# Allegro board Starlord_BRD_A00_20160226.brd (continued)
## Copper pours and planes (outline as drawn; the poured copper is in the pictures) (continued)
3D3V_S5_KBC on BOTTOM: 192.45,41.06 192.35,41.16 192.35,43.93 192.53,44.11 195.71,44.11 195.98,43.83 195.98,43.35 195.48,42.84 193.06,42.84 192.89,42.66 192.89,41.67 192.94,41.62 192.94,41.14 192.86,41.06
3D3V_S5_KBC on L5VCC: 186.31,27.08 186.04,27.35 186.04,28.33 186.69,28.99 191.39,28.99 192.01,29.6 192.01,32.43 189.74,34.7 186.82,34.7 185.17,36.35 181.45,36.35 179.69,34.59 179.69,29.89 179.04,29.24 178.82,29.24 178.55,29.51 178.55,36.84 185.04,43.34 187.45,43.34 190.07,45.95 194.55,45.95 194.55,42.3 197.85,39 197.85,37.73 200.9,34.68 200.9,33.7 200.5,33.3 199.9,33.3 197.87,35.34 196.19,35.34 194.92,34.07 194.15,34.07 192.77,32.68 192.77,29.13 191.87,28.22 187.93,28.22 186.79,27.08
3D3V_S5_PCH on TOP: 93.78,30.83 93.7,30.9 93.7,31.84 93.9,32.05 95.1,32.05 95.22,31.92 95.22,31.21 94.84,30.83
3D3V_S5_PCH on TOP: 113.69,14.01 113.43,14.27 113.43,14.34 109.47,18.3 109.47,18.89 109.65,19.07 109.78,19.07 110.67,18.18 111.61,18.18 112.72,17.06 120.72,17.06 121.03,16.76 121.03,15.97 120.83,15.76 120.57,15.76 120.47,15.87 120.47,16.15 120.29,16.32 115.03,16.32 114.3,15.59 114.3,14.27 114.04,14.01
3D3V_S5_PCH on TOP: 112.7,27.35 111.94,28.11 111.94,30.09 111.66,30.37 111.07,30.37 110.84,30.14 108.02,30.14 107.08,31.08 107.08,31.54 104.93,33.7 100.99,33.7 100.79,33.49 99.87,33.49 99.62,33.75 99.62,34.21 100.2,34.79 105.31,34.79 108.96,31.13 117.35,31.13 118.16,30.32 118.16,28.97 119.07,28.06 120.37,28.06 120.75,28.44 120.75,28.97 121.32,29.54 121.32,30.94 125.65,35.27 126.8,35.27 127.56,36.03 127.56,36.29 127.73,36.47 128.88,36.47 129.13,36.21 129.13,35.58 127.94,34.38 126.16,34.38 123.73,31.96 123.72,31.96 122.15,30.38 122.15,29.28 121.52,28.66 121.52,27.97 120.95,27.4 118.54,27.4 117.3,28.64 117.3,29.33 117.07,29.56 117.07,29.91 116.84,30.14 113.41,30.14 112.7,29.43 112.7,28.31 112.88,28.13 114.63,28.13 114.76,28.01 115.14,28.01 115.26,27.88 115.26,27.42 115.19,27.35
3D3V_S5_PCH on TOP: 100.61,14.04 100.51,14.14 100.51,14.32 100.76,14.57 101.24,14.57 101.42,14.75 101.42,15.87 101.47,15.92 102.28,15.92 103.05,15.16 103.05,14.19 102.89,14.04
3D3V_S5_PCH on BOTTOM: 113.59,10 113.49,10.1 113.49,11.27 113.59,11.37 113.59,14.44 113.74,14.6 114.2,14.6 114.6,14.19 115.14,14.19 115.62,13.71 115.62,13.17 114.97,12.53 114.97,11.92 114.53,11.47 114.53,10.23 114.3,10 ; 2 cut-outs
3D3V_S5_PCH on BOTTOM: 127.94,35.78 127.81,35.91 127.81,36.29 128.57,37.05 128.57,37.51 129.04,37.98 129.04,39.17 129.34,39.46 130.1,39.46 130.22,39.34 130.22,37.05 130.1,36.92 129.72,36.92 128.57,35.78
3D3V_S5_PCH on BOTTOM: 84.2,12.82 84.07,12.95 84.07,13.45 83.92,13.61 83.62,13.61 83.34,13.89 83.34,14.27 83.54,14.47 83.82,14.47 84.1,14.19 84.45,14.19 84.76,13.89 84.76,12.92 84.66,12.82
3D3V_S5_PCH on BOTTOM: 81.38,12.44 81,12.82 80.57,12.82 80.47,12.92 80.47,13.33 80.64,13.5 81.46,13.5 81.63,13.33 81.63,12.54 81.53,12.44
3D3V_S5_PCH on BOTTOM: 113.21,24.22 113.08,24.35 113.08,24.86 113.21,24.98 113.59,24.98 113.71,25.11 113.71,25.87 113.59,26 111.38,26 111.17,26.2 111.17,27.27 111.3,27.4 113.59,27.4 113.84,27.65 113.84,27.8 114.02,27.98 115.19,27.98 115.31,27.86 115.31,27.37 115.14,27.19 115.14,27.17 114.93,26.97 114.73,26.97 114.45,26.69 114.45,25.39 114.76,25.09 114.76,24.63 114.35,24.22 ; 4 cut-outs
3D3V_S5_PCH on L3: 107.62,14.39 108.2,14.98 110.11,14.98 111.73,13.35 113.66,13.35 114.15,13.83 114.15,14.55 113.97,14.72 113.59,14.72 113.23,14.37 113.23,14.16 113.08,14.01 112.11,14.01 110.29,15.84 107.11,15.84 106.68,15.41 105.69,15.41 104.85,14.57 100.71,14.57 100.51,14.37 100.51,13.89 100.58,13.81 105.31,13.81 105.89,14.39
3D3V_S5_PCH on L6: 78.97,9.95 78.76,10.15 78.76,10.63 81.89,13.76 81.89,14.14 82.29,14.55 83.72,14.55 83.92,14.34 83.92,13.58 80.29,9.95
3D3V_S5_PCH on L6: 97.2,34.54 100.18,34.54 100.61,34.1 100.61,33.65 99.97,33.01 97.1,33.01 96.7,33.42 96.7,34.03
3D3V_SEN_S0 on TOP: 56.64,91.51 56.59,91.56 56.59,92.12 56.36,92.35 56.36,92.63 55.32,93.67 54.2,93.67 52.09,95.77 52.09,98.67 52.37,98.95 54.41,98.95 54.58,98.77 54.58,98.04 55.29,97.32 56.18,97.32 56.41,97.1 56.41,94.56 56.72,94.25 56.72,93.36 57.36,92.71 57.36,92.16 57.2,91.99 57.2,91.56 57.15,91.51 ; 6 cut-outs
3D3V_SSD on TOP: 201.6,10.89 201.34,11.14 201.34,12.67 200.71,13.3 198.42,13.3 198.04,13.68 198.04,19.78 198.07,19.8 198.07,20.18 201.09,23.21 202.61,23.21 202.74,23.33 202.74,31.21 203.38,31.84 203.88,31.84 204.09,31.64 204.09,22.57 203.07,21.56 203.07,20.97 202.92,20.82 200.66,20.82 200.48,20.64 200.48,20.21 200.28,20.01 199.29,20.01 199.11,19.83 199.11,18.51 199.44,18.18 199.44,15.21 199.57,15.08 203.25,15.08 203.63,14.7 203.63,11.4 203.12,10.89 ; 11 cut-outs
3D3V_SSD on BOTTOM: 201.65,27.04 201.62,27.07 201.62,28.82 201.65,28.85 203.3,28.85 203.5,29.05 203.5,30.29 203.25,30.55 201.62,30.55 201.6,30.57 201.6,31.72 201.85,31.97 203.76,31.97 204.01,31.72 204.01,27.47 203.58,27.04
3D3V_SSD on BOTTOM: 202.11,11.9 201.6,12.41 201.6,14.32 203.5,14.32 203.63,14.19 203.63,12.28 203.25,11.9
81208_AGND on TOP: 153.74,91.3 153.69,91.36 153.69,91.76 153.92,91.98 153.92,95.62 153.91,95.62 153.91,96.85 153.68,97.08 153.38,97.08 153.11,97.35 153.11,98.59 152.93,98.77 152.75,98.77 152.68,98.85 152.68,99.33 152.78,99.43 153.62,99.43 153.92,99.13 153.92,98.44 154.05,98.31 154.05,98.31 154.43,97.93 156.54,97.93 156.56,97.96 157.12,97.96 157.25,97.83 157.25,97.65 157.48,97.43 158.9,97.43 159.61,98.14 161.92,98.14 162.05,98.01 162.05,97.4 161.97,97.32 160.07,97.32 159.54,96.79 159.54,94.86 159.69,94.71 159.69,93.41 159.56,93.29 159.15,93.29 159.03,93.41 159.03,93.87 158.77,94.12 158.11,94.12 158.03,94.04 158.03,92.89 157.85,92.71 154.78,92.71 154.62,92.55 154.62,92.15 154.53,92.07 154.53,92.07 154.25,91.79 154.25,91.38 154.18,91.3 ; 25 cut-outs
81208_AGND on BOTTOM: 154.38,92.93 154.2,93.11 154.2,97.3 154.4,97.5 158.62,97.5 158.77,97.35 158.77,93.08 158.62,92.93
+DC_IN on TOP: 21.28,76.17 20.98,76.47 20.98,77.31 21.36,77.69 22.4,77.69 23.29,78.58 23.29,78.96 23.82,79.49 23.82,81.55 23.93,81.65 23.93,82.52 23.8,82.64 22.17,82.64 21.97,82.85 21.97,83.96 22.05,84.04 25.32,84.04 25.7,83.66 25.7,81.04 26.9,79.85 29.01,79.85 29.13,79.72 29.13,76.8 28.5,76.17 ; 7 cut-outs
+DC_IN on BOTTOM: 21.92,75.25 21.77,75.4 21.77,75.99 21.89,76.12 23.47,76.12 23.72,76.37 24.38,76.37 25.45,77.44 25.45,79.16 25.88,79.59 26.34,79.59 26.59,79.34 26.59,76.67 26.34,76.42 25.6,76.42 24.43,75.25
+DC_IN_C on TOP: 21.21,84.29 20.92,84.59 20.92,87.38 21.26,87.72 24.94,87.72 25.58,87.09 25.58,84.67 25.2,84.29
+DC_IN_C on BOTTOM: 18.9,81.2 18.67,81.42 18.67,82.97 19.16,83.47 19.16,83.85 20.09,84.78 20.42,84.78 20.62,84.98 20.62,87.04 21.23,87.65 23.32,87.65 23.8,87.16 23.8,84.98 23.16,84.34 22.63,84.34 22.05,83.76 21.44,83.76 20.52,82.85 20.52,82.54 20.04,82.06 20.04,81.42 19.81,81.2 ; 3 cut-outs
+SDC_IN on TOP: 32.56,81.63 32.43,81.75 32.43,83.02 31.67,83.79 31.67,86.2 31.8,86.33 34.09,86.33 34.47,85.94 38.53,85.94 38.78,85.69 38.78,83.28 38.4,82.9 36.5,82.9 35.23,81.63
+V_EDRAM_VR on TOP: 114.83,69.05 114.64,69.24 114.64,70.31 115.24,70.91 115.24,71.59 115.29,71.64 116.03,71.64 116.25,71.42 116.71,71.42 117.02,71.11 117.02,69.31 116.76,69.05 ; 3 cut-outs
+V_EDRAM_VR on TOP: 106.86,94.2 106.73,94.33 106.73,96.1 106.86,96.23 110.67,96.23 110.92,95.98 110.92,94.45 110.67,94.2
+V_EDRAM_VR on BOTTOM: 115.11,70.2 114.48,70.83 114.48,71.34 114.73,71.59 114.86,71.59 115.37,71.09 116,71.09 116.38,71.47 116.64,71.47 117.02,71.09 117.78,71.09 118.16,71.47 118.67,71.47 118.79,71.34 118.79,70.45 118.54,70.2
+V_EDRAM_VR on L4: 116.76,78.2 119.05,78.2 119.94,77.31 119.94,71.21 118.79,70.07 115.62,70.07 114.73,70.96 113.08,70.96 112.32,71.72 112.32,75.15 111.3,76.17 111.3,83.91 110.16,85.06 110.16,93.44 109.65,93.95 109.02,93.95 108.25,94.71 108.25,96.36 108.76,96.87 114.35,96.87 115.87,95.34 115.87,79.09
+V_EOPIO_VR on TOP: 106.86,91.91 106.73,92.04 106.73,93.69 106.86,93.82 109.65,93.82 109.9,93.56 109.9,92.04 109.78,91.91
+V_EOPIO_VR on TOP: 111.56,68.93 111.19,69.3 111.19,70.34 111.3,70.45 111.68,70.45 112.06,70.83 112.7,70.83 112.83,70.7 112.83,70.53 113.18,70.17 114.22,70.17 114.4,69.99 114.4,69.21 114.12,68.93 ; 3 cut-outs
+V_EOPIO_VR on BOTTOM: 111.43,69.82 111.17,70.07 111.17,70.32 111.58,70.73 111.68,70.73 111.91,70.96 111.91,71.11 111.81,71.21 111.81,71.34 111.94,71.47 112.95,71.47 113.08,71.34 113.08,70.58 112.95,70.45 112.04,70.45 112.01,70.43 112.01,69.89 111.94,69.82
+V_EOPIO_VR on L4: 107.24,93.44 109.52,93.44 109.9,93.06 109.9,84.67 110.79,83.79 110.79,76.29 111.81,75.28 111.81,71.85 112.83,70.83 112.83,69.69 112.44,69.31 110.16,69.31 108.89,70.58 108.89,74.51 108.38,75.02 108.38,80.74 106.48,82.64 106.48,92.68
AD+ on TOP: 26.97,80.1 26.85,80.23 26.85,82.97 27.1,83.23 27.1,87.82 27.18,87.9 29.69,87.9 30.53,88.74 30.53,89.53 30.94,89.93 31.09,89.93 31.29,90.14 31.29,90.9 31.42,91.02 32.05,91.02 32.31,90.77 32.31,88.48 31.55,87.72 31.55,83.66 30.78,82.9 30.78,80.48 30.4,80.1 ; 6 cut-outs
AD+ on TOP: 149.27,31.72 149.2,31.79 149.15,31.79 148.89,32.05 148.89,32.35 149.25,32.71 149.91,32.71 149.92,32.72 150.28,32.72 151.43,33.87 151.43,38.8 151.18,39.06 150.24,39.06 149.99,39.31 149.99,40.02 150.04,40.07 151.66,40.07 152.45,39.29 152.45,33.24 150.93,31.72
AD+ on BOTTOM: 147.52,29.81 147.34,29.99 147.34,30.8 147.47,30.93 147.85,30.93 148.94,32.02 148.94,32.48 148.84,32.58 148.36,32.58 148.33,32.6 148.33,33.11 148.39,33.16 149.6,33.16 149.71,33.06 149.71,31.61 149.05,30.95 148.66,30.95 148.36,30.65 148.36,30.01 148.16,29.81
AUD_AGND on TOP: 13.82,9.62 13.69,9.74 13.69,11.5 14.12,11.93 14.12,13.86 14.3,14.04 15.49,14.04 15.54,13.99 15.54,13.5 15.44,13.4 14.88,13.4 14.78,13.3 14.78,12.18 15.01,11.95 15.34,11.95 15.44,11.85 15.44,11.35 15.42,11.32 14.68,11.32 14.4,11.04 14.4,9.72 14.3,9.62
AUD_AGND on BOTTOM: 18.18,16.86 18.01,17.03 18.01,18.43 17.75,18.69 17.22,18.69 17.09,18.81 17.09,20.9 17.32,21.12 17.58,21.12 17.93,21.48 18.79,21.48 18.9,21.38 18.9,21.07 18.74,20.92 18.13,20.92 18.03,20.82 18.03,20.21 18.18,20.06 19.99,20.06 20.27,19.78 21.59,19.78 21.72,19.65 21.72,18.71 21.59,18.58 20.7,18.58 20.24,19.04 19.2,19.04 19.07,18.91 19.07,17.34 18.59,16.86 ; 9 cut-outs
AUD_AGND on L2GND: 13.59,9.68 12.96,10.32 3.3,10.32 2.53,11.09 2.53,11.98 2.98,12.22 3.3,12.63 12.9,12.63 13.87,13.38 13.41,14.51 13.41,19.57 13.87,20.7 12.9,21.45 4.15,21.45 5.84,23.14 9.65,23.14 10.03,23.52 14.73,23.52 16,24.79 18,24.79 18.02,24.78 18.02,24.3 17.88,24.16 17.5,24.16 17.13,23.79 17.13,23.16 16.75,22.78 16.75,21.98 16.99,21.75 17.91,21.75 18.27,22.11 18.27,22.87 19.16,23.76 19.16,24.52 19.56,24.92 20.04,24.92 20.54,24.41 22.48,24.41 22.61,24.54 24.61,24.54 24.62,24.52 24.62,21.73 25.12,21.24 25.5,21.24 25.51,21.22 25.51,21 25,20.49 25,19.73 24.86,19.59 21.05,19.59 20.69,19.22 20.69,15 21.05,14.63 22.2,14.63 22.34,14.49 22.34,13.38 22.08,13.13 22.08,12.49 21.94,12.35 18.77,12.35 18.51,12.09 17.88,12.09 17.24,11.46 17.15,11.46 16.64,11.97 15.97,11.97 15.46,11.46 14.7,11.46 14.34,11.09 14.34,9.7 14.32,9.68
AUD_AGND on L7GND: outline of 82 points within 2.8,10.32 29.32,25.05
AUD_SPK_L+ on TOP: 18.51,9.24 18.36,9.39 18.36,10.23 18.91,10.77 19.82,10.77 20.14,11.09 20.52,11.09 20.85,11.42 20.85,11.9 20.93,11.98 22.1,11.98 22.43,12.31 22.76,12.31 22.86,12.21 22.86,11.65 22.34,11.13 21.7,11.13 20.45,9.87 19.43,9.87 19.35,9.8 19.35,9.34 19.25,9.24 ; 3 cut-outs
AUD_SPK_L+_C on TOP: 15.34,7 14.98,7.36 14.98,7.99 16.38,9.39 16.38,9.95 16.74,10.3 17.96,10.3 18.03,10.23 18.03,9.31 17.85,9.14 17.4,9.14 16.66,8.4 16.66,7.18 16.48,7 ; 4 cut-outs
AUD_SPK_L- on TOP: 18.74,7.66 18.67,7.74 18.67,8.93 18.79,9.06 19.3,9.06 19.51,9.26 19.51,9.44 19.73,9.67 20.5,9.67 21.79,10.96 22.38,10.96 23.06,11.65 23.47,11.65 23.62,11.5 23.62,10.68 22.87,9.94 22.21,9.94 20.7,8.42 19.76,8.42 19.58,8.25 19.58,7.74 19.51,7.66 ; 3 cut-outs
AUD_SPK_L-_C on TOP: 14.46,5.59 13.92,6.14 13.92,7.69 14.07,7.84 14.58,7.84 14.91,7.51 14.91,7.28 15.47,6.72 16.58,6.72 16.89,7.03 16.89,8.25 17.35,8.7 18.29,8.7 18.36,8.63 18.36,8.14 18.46,8.04 18.46,6.93 18.36,6.82 18.01,6.82 17.85,6.67 17.85,6.19 17.26,5.59 ; 3 cut-outs
AUD_SPK_R+ on TOP: 17.65,1.92 17.5,2.07 17.5,3.34 17.78,3.62 19.33,3.62 19.92,4.22 19.92,5.21 21.36,6.65 21.36,6.85 24.92,10.41 25.27,10.41 25.6,10.08 25.6,9.85 22.43,6.67 22.43,6.34 21.46,5.38 21.46,4.89 20.98,4.41 20.98,3.62 20.14,2.79 18.62,2.79 18.46,2.63 18.46,2.4 17.98,1.92 ; 2 cut-outs
AUD_SPK_R+_C on TOP: 13.16,1.19 11.3,3.04 11.3,7.38 11.45,7.54 12.19,7.54 12.46,7.27 12.46,4.7 12.47,4.69 12.47,3.83 14.04,2.25 15.29,2.25 15.47,2.43 15.47,2.58 15.59,2.71 16.1,2.71 16.28,2.89 16.28,3.47 16.36,3.55 17.12,3.55 17.22,3.45 17.22,2.28 16.13,1.19 ; 4 cut-outs
AUD_SPK_R- on TOP: 18.49,3.83 18.34,3.98 18.34,4.94 18.08,5.2 18.08,5.63 18.21,5.76 18.82,5.76 19.3,6.24 19.3,6.34 20.72,7.76 20.72,8.09 22.22,9.59 22.78,9.59 23.77,10.58 23.77,11.93 23.9,12.06 24.46,12.06 24.53,11.98 24.53,10.25 23.29,9.01 23.16,9.01 21.13,6.98 21.13,6.62 19.77,5.26 19.77,4.35 19.25,3.83 ; 2 cut-outs
AUD_SPK_R-_C on TOP: 14.07,3.5 12.62,4.94 12.62,7.54 12.85,7.76 13.46,7.76 13.79,7.43 13.79,5.99 14.55,5.22 17.65,5.22 18.01,4.87 18.01,3.95 17.88,3.83 15.37,3.83 15.04,3.5 ; 3 cut-outs
BT+ on TOP: 154.99,25.37 154.96,25.39 153.85,25.39 153.36,25.87 153.36,28.67 154.25,29.56 158.8,29.56 158.8,29.51 159.31,29 159.31,27.04 157.63,25.37
BT+ on BOTTOM: 153.85,25.37 153.08,26.13 153.08,28.92 153.34,29.18 153.34,30.45 153.21,30.57 153.21,31.72 153.97,32.48 153.97,36.92 152.84,38.05 150.05,38.05 149.88,37.89 149.88,37.58 149.76,37.46 148.87,37.46 148.77,37.56 148.77,40.2 149.17,40.61 150.42,40.61 150.52,40.5 150.87,40.5 151.08,40.3 151.08,39.34 151.29,39.12 152.23,39.12 152.32,39.21 152.32,40.35 152.58,40.61 156.26,40.61 156.51,40.35 156.51,38.8 156.16,38.45 156.16,30.8 156.26,30.7 160.83,30.7 161.19,30.34 161.19,28.13 160.7,27.65 160.7,25.62 160.45,25.37 ; 14 cut-outs
CAP_LED#_R on L3: 194.49,31.72 194.92,31.28 194.92,30.52 194.31,29.91 193.22,29.91 191.84,31.28 191.84,32.07 191.97,32.2 192.3,32.2 192.81,31.69 193.57,31.69 193.6,31.72
CFG_RCOMP on TOP: 121.16,68.9 120.88,69.18 120.88,70.17 120.98,70.27 122.93,70.27 123.19,70.02 123.19,69.26 122.83,68.9 ; 1 cut-out
CHARGER_SRC on TOP: 140.26,46.7 139.62,47.34 139.62,50.77 139.75,50.89 145.21,50.89 145.46,50.64 145.46,47.08 145.08,46.7
CHARGER_SRC on BOTTOM: 137.72,46.45 137.59,46.57 137.59,47.72 137.97,48.1 138.61,48.1 139.11,48.61 139.11,52.29 139.24,52.42 140.26,52.42 140.64,52.04 140.64,51.15 140.87,50.92 143.03,50.92 143.56,50.38 143.56,46.68 143.33,46.45 ; 3 cut-outs
DCBATOUT on TOP: outline of 194 points within 34.59,44.29 179.37,112.74 ; 24 cut-outs
DCBATOUT on TOP: outline of 84 points within 48.82,0.75 161.76,22.42 ; 5 cut-outs
DCBATOUT on BOTTOM: 141.02,51.15 140.77,51.4 140.77,52.67 140.89,52.8 143.18,52.8 143.43,52.54 143.43,51.4 143.18,51.15
DCBATOUT on BOTTOM: 58.6,99.79 58.22,100.17 58.22,101.95 59.1,102.84 76.25,102.84 78.66,105.25 78.66,109.06 80.95,111.34 89.58,111.34 90.02,110.91 90.02,106.95 88.95,105.88 83.87,105.88 81.08,103.09 79.22,103.09 77.52,101.39 67.69,101.39 66.47,100.17 63.04,100.17 62.66,99.79
DCBATOUT on BOTTOM: 109.52,7.2 109.4,7.33 109.4,8.73 109.65,8.98 112.57,8.98 112.95,8.6 112.95,7.97 112.19,7.2
DCBATOUT on BOTTOM: 159.18,66.51 158.8,66.89 156.89,66.89 156.51,67.28 154.74,67.28 154.61,67.4 154.61,70.07 154.86,70.32 162.86,70.32 163.63,71.09 163.63,80.99 162.74,81.88 159.18,81.88 158.8,82.26 158.8,82.52 157.91,83.4 157.88,83.4 157.58,83.71 155.85,83.71 155.55,83.4 154.86,83.4 154.74,83.53 154.74,85.49 154.91,85.67 156.94,85.67 157.1,85.82 168.2,85.82 168.32,85.94 168.32,91.43 167.31,92.45 167.31,98.77 165.78,100.3 165.78,103.34 162.1,107.03 155.88,107.03 155.12,107.79 146.61,107.79 144.58,105.76 144.58,102.96 147.5,100.04 147.5,96.61 147.88,96.23 149.15,96.23 149.4,95.98 149.4,94.96 149.02,94.58 143.56,94.58 143.43,94.71 143.43,97.5 143.42,97.51 143.42,97.69 143.18,97.93 143.18,100.17 141.91,101.44 140.89,101.44 140.64,101.69 140.64,107.66 142.92,109.95 162.74,109.95 167.87,104.82 167.87,101.92 169.85,99.94 169.85,93.54 170.48,92.9 170.48,83.28 169.98,82.77 169.98,75.45 171.3,74.13 177.09,74.13 177.21,74.01 177.21,71.95 175.46,70.2 167.44,70.2 163.75,66.51 ; 7 cut-outs
DCBATOUT on BOTTOM: 154.89,57.78 154.74,57.93 154.74,63.08 155.75,64.1 161.85,64.1 161.97,63.97 161.97,62.65 161.9,62.58 156.51,62.58 156.26,62.32 156.26,58.51 155.95,58.21 155.7,58.21 155.27,57.78 ; 1 cut-out
DCBATOUT on BOTTOM: 158.98,20.29 158.55,20.72 158.55,23.05 159.43,23.94 161.36,23.94 161.75,23.56 164.59,23.56 164.97,23.94 168.93,23.94 170.36,25.37 174.06,25.37 174.29,25.59 174.29,36.67 174.17,36.8 174.17,57.73 174.75,58.31 177.29,58.31 177.48,58.12 177.48,49.51 176.71,48.73 176.71,46.55 177.82,45.43 177.82,40.61 177.4,40.19 177.4,37.46 177.98,36.88 177.98,35.5 176.71,34.23 176.71,24.35 175.56,23.21 172.64,23.21 170.55,21.11 163.03,21.11 162.2,20.29 ; 1 cut-out
DCBATOUT on BOTTOM: 153.72,47.59 153.47,47.84 153.47,48.89 153.29,49.06 152.96,49.06 152.68,49.34 152.68,50.51 152.87,50.7 153.76,50.7 153.77,50.72 154.94,50.72 155.45,50.21 156.06,50.21 156.39,49.88 156.39,47.72 156.26,47.59
DCBATOUT on BOTTOM: 48.94,10.68 48.84,10.79 48.84,12.82 49.05,13.02 51.41,13.02 51.61,12.82 51.61,11.12 51.18,10.68
DCBATOUT on L4: 140.77,51.78 142.92,51.78 143.56,52.42 144.7,52.42 145.34,51.78 148.64,51.78 151.18,49.24 153.21,49.24 153.59,48.86 153.59,47.97 153.72,47.84 155.75,47.84 155.88,47.97 155.88,50.89 154.86,51.91 152.07,51.91 149.91,54.07 140.77,54.07 140.38,53.69 140.38,52.16
DCBATOUT on L5VCC: 35.56,87.15 35.04,87.67 35.04,96.66 41.02,102.65 76.46,102.65 78.87,105.06 82.81,105.06 86.74,109 88.62,109 88.89,108.73 88.89,104.82 84.55,100.49 77.95,100.49 77.57,100.11 67.44,100.11 67.06,100.49 62.2,100.49 61.31,99.6 44.42,99.6 38.47,93.64 38.47,87.8 37.82,87.15
DCBATOUT on L6: 163.24,44.29 162.99,44.54 162.99,45.81 162.74,46.07 155.12,46.07 153.59,47.59 153.59,48.53 152.8,49.32 152.8,50.18 153.12,50.5 155.64,50.5 155.75,50.38 155.75,49.11 156.39,48.48 163.75,48.48 164.51,49.24 164.51,57.5 171.25,64.23 171.27,64.23 171.93,64.89 176.81,64.89 177.72,63.97 179.25,63.97 179.5,63.72 179.5,55.72 178.74,54.96 176.83,54.96 176.58,55.21 176.58,58 177.34,58.77 177.34,61.43 176.58,62.2 174.93,62.2 169.21,56.48 169.21,47.97 168.2,46.96 167.31,46.96 166.8,46.45 166.8,46.07 165.02,44.29
DCBATOUT_+VCCSA on BOTTOM: 146.61,57.88 146.35,58.13 146.35,61.56 146.48,61.69 149.91,61.69 149.93,61.66 153.03,61.66 153.82,62.45 154.35,62.45 154.48,62.32 154.48,59.15 154.35,59.02 149.91,59.02 149.53,58.64 149.53,58.26 149.15,57.88 ; 2 cut-outs
DCBATOUT_CAMERA on TOP: 54.79,90.14 54.53,90.39 54.53,93.44 54.63,93.54 55.27,93.54 56.2,92.61 56.2,92.28 56.49,91.99 56.49,90.82 55.8,90.14 ; 4 cut-outs
DCBATOUT_CAMERA on BOTTOM: 55.45,91.53 54.96,92.02 54.96,93.49 55.01,93.54 55.75,93.54 55.8,93.49 55.8,92.52 55.9,92.42 56.31,92.42 56.46,92.27 56.46,91.66 56.34,91.53
DCBATOUT_LCD on TOP: 76.1,92.68 75.61,93.16 75.61,93.56 75.23,93.95 73.53,93.95 73.05,94.43 73.05,96.18 73.07,96.21 78.81,96.21 79.07,95.95 79.81,95.95 79.96,95.8 79.96,93.08 79.55,92.68 ; 6 cut-outs
DCBATOUT_LCD on BOTTOM: 77.16,93.18 76.99,93.36 76.99,93.97 77.32,94.3 78.61,94.3 78.79,94.48 78.79,95.44 78.89,95.55 80.52,95.55 80.62,95.44 80.62,93.54 80.26,93.18
EC_AGND on BOTTOM: 189.74,26.81 189.61,26.94 189.61,27.86 189.38,28.08 189.38,28.57 189.43,28.62 190.78,28.62 190.88,28.52 190.88,26.84 190.85,26.81
EC_AGND on BOTTOM: 186.97,31.13 186.41,31.69 186.41,32.15 186.49,32.22 187.73,32.22 187.86,32.35 188.24,32.35 188.8,31.79 189.36,31.79 189.48,31.67 189.48,31.23 189.38,31.13 ; 3 cut-outs
EC_AGND on L4: 187.73,32.45 188.31,32.45 189.76,31 189.99,31 190.85,30.14 190.85,27.17 190.78,27.09 189.96,27.09 189.03,28.03 189.03,30.29 187.5,31.82 187.5,32.22
EDP_COMP on L3: 114.25,67.73 113.54,67.73 113.26,67.45 113.26,65.42 115.09,63.59 118.54,63.59 119.15,62.98 121.38,62.98 121.99,63.59 123.9,63.59 124.1,63.8 124.1,64.51 123.26,65.35 122.05,65.35 121.46,64.76 115.26,64.76 114.37,65.65 114.37,67.61
EDRAM_OPIO_RCOMP on TOP: 121.44,73.3 121.36,73.37 121.36,73.85 121.13,74.08 120.7,74.08 120.6,74.18 120.6,74.64 120.67,74.72 121.13,74.72 121.49,74.36 121.84,74.36 121.97,74.49 122.22,74.49 122.3,74.41 122.3,74.11 121.89,73.7 121.89,73.42 121.77,73.3
FAN_VCC_1 on BOTTOM: 149.15,73.63 148.77,74.01 148.77,76.55 149.76,77.54 151.31,77.54 151.92,76.93 153.21,76.93 153.97,77.69 156.77,77.69 156.89,77.56 156.89,76.93 156.77,76.8 155.24,76.8 154.86,76.42 154.86,74.64 154.35,74.13 151.31,74.13 150.8,73.63 ; 8 cut-outs
JGND on TOP: 17.58,78.96 17.32,79.21 17.32,82.24 17.55,82.47 17.55,85.97 17.78,86.2 20.45,86.2 20.65,86 20.65,83.2 19.94,82.49 19.94,80.31 18.59,78.96
JGND on BOTTOM: 16.51,80.86 16.41,80.97 16.41,81.42 15.8,82.03 15.8,86.61 15.87,86.68 18.24,86.68 18.39,86.53 18.39,85.23 18.92,84.7 18.92,83.48 18.49,83.05 18.49,81.37 17.98,80.86 ; 5 cut-outs
LCDVDD on TOP: 82.19,92.42 81.84,92.78 81.84,95.47 81.76,95.55 81.76,95.7 81.58,95.88 81.58,99.36 81.84,99.61 83.67,99.61 83.82,99.46 83.82,98.98 83.69,98.85 82.19,98.85 81.99,98.64 81.99,96.51 82.9,95.6 83.11,95.6 83.51,95.19 83.51,94.58 83.92,94.17 83.92,93.74 83.69,93.51 83.69,92.88 83.23,92.42 ; 5 cut-outs
LCDVDD on BOTTOM: 81.38,93.69 81.28,93.79 81.28,95.39 81.38,95.5 83.03,95.5 83.16,95.37 83.16,93.77 83.08,93.69
M_VREF_CA_DIMMA on TOP: 65.2,44.42 64.95,44.67 64.95,45.43 66.17,46.65 71.63,46.65 71.8,46.83 71.8,48.23 71.93,48.35 72.31,48.35 72.57,48.1 72.57,46.96 73.2,46.32 73.2,45.56 73.07,45.43 71.35,45.43 70.81,45.97 66.75,45.97 65.96,45.18 65.96,44.67 65.71,44.42
M_VREF_CA_DIMMB on TOP: 50.09,40.35 49.96,40.48 49.96,41.49 50.34,41.88 50.72,41.88 50.85,42 50.85,43.27 51.48,43.91 51.48,44.92 51.74,45.18 52.37,45.18 52.63,44.92 52.63,41.49 51.48,40.35 ; 4 cut-outs
PWR_1D0V_PH on BOTTOM: 95.93,1.87 95.55,2.25 95.55,8.47 95.81,8.73 98.98,8.73 99.24,8.47 99.24,3.65 99.36,3.52 99.87,3.52 100,3.65 100,3.8 100.02,3.83 101.01,3.83 101.17,3.98 101.17,4.61 101.22,4.66 104.82,4.66 105.21,4.28 105.21,3.67 105.05,3.52 104.11,3.52 104.09,3.55 102.11,3.55 101.95,3.39 101.95,2.18 101.65,1.87
PWR_1D2V_LDO_P5 on BOTTOM: 45.64,3.14 45.39,3.39 45.39,6.32 45.77,6.7 47.04,6.7 47.17,6.57 47.17,6.19 46.66,5.68 46.66,3.39 46.4,3.14
PWR_1D2V_PGOOD on BOTTOM: 50.98,4.92 50.21,5.68 49.2,5.68 48.69,6.19 48.69,6.57 48.82,6.7 49.96,6.7 50.98,5.68 52.12,5.68 52.25,5.55 52.25,5.05 52.12,4.92
PWR_1D2V_PHASE on BOTTOM: 42.59,2.76 42.34,3.01 42.34,6.19 44.12,7.97 44.12,8.22 44.37,8.47 46.4,8.47 47.17,7.71 47.17,7.33 47.04,7.2 45.77,7.2 45.26,6.7 45.26,3.01 45.01,2.76 ; 2 cut-outs
PWR_2D5V on TOP: 45.92,97.63 45.26,98.29 45.26,99.89 45.34,99.97 45.77,99.97 45.9,99.84 45.9,98.57 46.2,98.26 46.89,98.26 47.04,98.42 47.67,98.42 47.75,98.34 47.75,97.93 47.45,97.63
PWR_2D5V on BOTTOM: 45.26,97.76 45.13,97.88 45.13,99.79 47.17,99.79 47.55,100.17 47.55,101.18 47.67,101.31 50.87,101.31 50.98,101.21 50.98,100.45 50.85,100.32 50.52,100.32 50.42,100.22 50.42,98.59 50.34,98.52 49.33,98.52 48.56,97.76
PWR_3D3V on TOP: 159.05,48.86 158.8,49.11 158.8,51.65 159.05,51.91 164.82,51.91 165.01,51.72 165.01,49.1 164.77,48.86
PWR_3D3V on BOTTOM: 158.04,47.59 157.28,48.35 157.28,53.31 157.53,53.56 159.18,53.56 160.83,51.91 164.01,51.91 164.26,52.16 165.35,52.16 165.35,51.48 165.28,51.4 165.05,51.4 165.05,48.94 165.28,48.71 165.28,47.84 165.02,47.59 ; 1 cut-out
PWR_3D3V_LDO on BOTTOM: 163.07,55.85 162.51,56.4 161.69,56.4 161.59,56.51 161.59,57.62 162.1,57.62 162.48,57.24 165.4,57.24 165.53,57.12 165.53,56.1 165.28,55.85 ; 2 cut-outs
PWR_3D3V_PH on BOTTOM: 160.32,53.43 159.82,53.94 158.06,53.94 157.76,54.25 157.76,55.06 158.04,55.34 158.8,55.34 158.95,55.49 158.95,56.91 159.21,57.17 159.99,57.17 160.45,57.62 160.96,57.62 160.96,55.64 161.09,55.52 162.43,55.52 162.61,55.34 162.61,53.56 162.48,53.43 ; 1 cut-out
PWR_5V on TOP: 108.76,102.84 108.51,103.09 108.51,108.3 109.02,108.8 114.48,108.8 114.78,108.5 114.78,103.01 114.6,102.84
PWR_5V on BOTTOM: 107.59,100.3 107.34,100.55 107.34,101.44 108.51,102.61 108.51,108.47 106.78,110.2 106.68,110.2 106.63,110.25 106.63,110.89 106.75,111.01 107.11,111.01 107.29,110.84 116.79,110.84 116.94,110.68 116.94,109.85 116.41,109.31 116.41,108.98 114.78,107.36 114.78,102.45 113.1,100.78 111.53,100.78 111.05,100.3 ; 3 cut-outs
PWR_5V_PH on TOP: 103.73,102.84 103.35,103.22 103.35,104.36 102.46,105.25 102.46,106.01 102.33,106.14 100.56,106.14 100.43,106.26 100.43,106.65 102.08,108.3 102.92,108.3 103.05,108.42 103.05,109.31 103.2,109.47 105.98,109.47 106.82,108.63 106.82,103.38 106.27,102.84 ; 2 cut-outs
PWR_5V_PH on BOTTOM: 103.73,102.84 103.35,103.22 103.35,104.36 102.54,105.17 102.54,108.8 103.17,109.44 105.99,109.44 106.91,108.53 106.91,103.22 106.53,102.84
PWR_5V_VCC on TOP: 102.11,102.35 101.95,102.51 101.95,103.6 100.43,105.12 100.43,105.5 100.56,105.63 101.6,105.63 101.7,105.53 101.7,104.94 102.23,104.41 102.67,104.41 103.1,103.98 103.1,102.48 102.97,102.35
PWR_+VCCSA on BOTTOM: 134.54,53.56 134.42,53.69 134.42,58.92 134.52,59.02 134.82,59.02 135.08,59.27 138.23,59.27 138.48,59.02 138.48,54.32 138.1,53.94 135.3,53.94 134.92,53.56
PWR_CHG_HIDRV on L6: 145.54,37.89 146.4,37.89 147.17,38.65 147.17,40.53 146.91,40.78 145.69,40.78 145.11,40.2 145.11,38.35 145.54,37.91
PWR_CHG_LODRV on TOP: 141.58,42.84 141.17,43.25 141.17,43.73 141.83,44.39 142.26,44.39 142.47,44.19 142.47,43.73 142.59,43.6 143.86,43.6 143.91,43.55 143.91,43.1 143.66,42.84
PWR_CHG_LODRV on L6: 143.41,37.89 143.94,37.89 144.12,38.07 144.12,38.78 142.06,40.83 142.06,42.36 142.67,42.97 142.67,44.09 142.39,44.37 141.86,44.37 141.25,43.76 141.25,40.05
PWR_CHG_PHASE on TOP: 144.19,37.81 144.07,37.94 144.07,38.73 144.63,39.29 144.63,39.54 144.73,39.64 145.62,39.64 145.74,39.51 145.74,38.9 145.59,38.75 145.29,38.75 145.01,38.47 145.01,38.12 144.96,38.07 144.83,38.07 144.58,37.81 ; 1 cut-out
PWR_CHG_PHASE on TOP: 144.32,42.51 144.19,42.64 144.19,46.07 144.45,46.32 145.34,46.32 145.85,46.83 145.85,49.24 145.97,49.37 147.12,49.37 147.6,49.85 148.69,49.85 148.89,49.65 148.89,49.11 148.39,48.61 148.39,45.18 148.89,44.67 148.89,42.89 148.51,42.51
PWR_CHG_PHASE on BOTTOM: 145.72,42.64 144.45,43.91 144.45,49.5 144.7,49.75 148.64,49.75 148.89,49.5 148.89,49.11 148.39,48.61 148.39,45.18 148.89,44.67 148.89,43.02 148.51,42.64
PWR_CHG_PHASE on L6: 144.42,38.52 144.68,38.52 145.06,38.14 145.06,37.84 145.24,37.66 147.65,37.66 147.75,37.56 147.75,36.19 147.39,35.83 144.78,35.83 144.27,36.34 144.27,38.37
PWR_CHG_PHASE on L6: 149.91,42.64 149.91,41.62 149.53,41.24 148.77,41.24 147.12,42.89 147.12,44.8 147.37,45.05 148.64,45.05 148.77,44.92 148.77,43.78
PWR_CHG_PHASE_1 on BOTTOM: 152.58,40.73 152.32,40.99 152.32,43.02 149.78,45.56 149.78,48.48 150.06,48.76 153.16,48.76 153.16,47.39 153.34,47.21 157.4,47.21 157.66,46.96 157.66,41.37 157.02,40.73
PWR_DCBATOUT_1D0V on TOP: 105.59,3.78 105.33,4.03 105.33,4.41 104.95,4.79 101.27,4.79 101.01,5.05 101.01,6.19 101.14,6.32 104.57,6.32 105.21,6.95 109.78,6.95 110.16,6.57 110.16,4.16 109.78,3.78 ; 2 cut-outs
PWR_DCBATOUT_1D0V on BOTTOM: 105.59,3.78 105.33,4.03 105.33,4.41 104.95,4.79 101.27,4.79 101.14,4.92 101.14,5.43 101.01,5.55 100,5.55 100,5.81 101.01,5.81 101.09,5.88 101.09,6.27 101.14,6.32 104.57,6.32 105.21,6.95 109.35,6.95 109.45,7.05 111.68,7.05 111.76,6.98 111.76,6.42 110.74,5.4 110.74,3.88 110.64,3.78 ; 2 cut-outs
PWR_DCBATOUT_1D2V on TOP: 48.59,8.42 48.44,8.58 48.44,10.41 48.58,10.55 51.32,10.55 51.43,10.43 51.43,8.68 51.18,8.42
PWR_DCBATOUT_1D2V on BOTTOM: 47.42,7.71 47.29,7.84 47.29,9.11 47.8,9.62 48.56,9.62 48.69,9.74 48.69,10.51 48.82,10.63 51.74,10.63 51.87,10.51 51.87,9.54 51.99,9.41 54.18,9.41 54.3,9.29 54.3,8.45 54.07,8.22 49.2,8.22 48.69,7.71 ; 1 cut-out
PWR_DCBATOUT_3D3V on TOP: 158.67,59.78 158.55,59.91 158.55,62.07 158.8,62.32 160.42,62.32 160.58,62.17 160.58,61.54 160.07,61.03 160.07,60.16 159.69,59.78
PWR_DCBATOUT_3D3V on BOTTOM: 157.78,57.75 157.53,58 157.53,62.2 157.66,62.32 160.45,62.32 160.58,62.2 160.58,61.56 160.07,61.05 160.07,59.66 160.45,59.27 160.45,58 160.32,57.88 158.67,57.88 158.55,57.75 ; 4 cut-outs
PWR_DCBATOUT_5V on TOP: 98.91,106.65 98.4,107.15 90.47,107.15 90.22,107.41 90.22,109.14 90.69,109.61 98.61,109.61 100.3,107.92 100.3,106.77 100.18,106.65 ; 8 cut-outs
PWR_DCBATOUT_5V on BOTTOM: 90.47,107.03 90.4,107.1 90.4,109.95 91.79,111.34 97.08,111.34 97.71,110.71 97.71,108.3 96.44,107.03
PWR_VCCGT_GL1 on BOTTOM: 151.18,81.37 150.93,81.63 150.93,82.77 151.05,82.9 151.81,82.9 151.94,82.77 151.94,81.5 151.81,81.37
PWR_VCCGT_GL2 on BOTTOM: 139.5,92.55 139.37,92.68 139.37,93.82 139.62,94.07 140.38,94.07 140.51,93.95 140.51,92.68 140.38,92.55
PWR_VCCGT_PHASEDA on BOTTOM: 156.13,81.63 156.01,81.75 154.99,81.75 154.86,81.88 154.86,82.77 154.99,82.9 156.39,82.9 156.46,82.97 156.46,83.43 156.51,83.48 157.35,83.48 157.4,83.43 157.4,81.75 157.28,81.63 ; 1 cut-out
PWR_VCCGT_PHASEDB on BOTTOM: 145.21,91.41 145.08,91.53 145.08,92.42 144.58,92.93 143.69,92.93 143.56,93.06 143.56,94.07 144.58,94.07 146.1,92.55 146.1,91.53 145.97,91.41
PWR_VCCGT_SWA on BOTTOM: 147.24,79.72 146.99,79.98 146.99,87.98 147.24,88.23 148.39,88.23 148.51,88.1 148.51,86.58 148.77,86.33 151.43,86.33 151.81,85.94 151.81,83.15 151.69,83.02 150.93,83.02 150.8,82.9 150.8,80.61 149.91,79.72
PWR_VCCGT_SWB on BOTTOM: 135.91,92.57 135.81,92.68 135.81,97.5 136.19,97.88 137.59,97.88 137.97,98.26 137.97,99.79 138.1,99.91 140.13,99.91 140.51,99.53 140.51,94.33 140.38,94.2 139.62,94.2 139.11,93.69 139.11,92.68 139.01,92.57
PWR_VCCSA_DRVL on BOTTOM: 148.39,52.8 148,53.18 148,54.45 148.13,54.58 149.27,54.58 149.4,54.45 149.4,53.18 149.02,52.8
PWR_VCCSA_SW on BOTTOM: 141.65,52.92 141.02,53.56 141.02,59.15 142.29,60.42 145.97,60.42 146.1,60.29 146.1,58 146.73,57.37 147.5,57.37 147.75,57.12 147.75,53.43 147.24,52.92
PWR_VCORE_GL on BOTTOM: 150.8,65.24 150.54,65.5 150.54,66.51 150.8,66.77 151.56,66.77 151.69,66.64 151.69,65.37 151.56,65.24
PWR_VCORE_PHASED on BOTTOM: 156.13,65.5 155.88,65.75 154.74,65.75 154.61,65.88 154.61,66.77 154.74,66.89 155.75,66.89 156.01,66.64 157.66,66.64 157.78,66.51 157.78,65.62 157.66,65.5
PWR_VCORE_SW on BOTTOM: 148.51,62.2 148.26,62.45 148.26,64.1 148.13,64.23 146.96,64.23 146.73,64.46 146.73,70.58 147.52,71.37 150.39,71.37 151.56,70.2 151.56,67.02 151.43,66.89 150.67,66.89 150.29,66.51 150.29,63.97 149.91,63.59 149.91,62.45 149.66,62.2
RING2 on TOP: 16,14.9 15.85,15.05 15.85,15.61 15.59,15.87 14.96,15.87 14.91,15.92 14.91,17.57 15.29,17.95 15.29,18.48 15.64,18.84 16.64,18.84 16.74,18.74 16.74,18.48 16.66,18.41 15.92,18.41 15.82,18.3 15.82,16.55 16.74,15.64 16.74,14.98 16.66,14.9 ; 1 cut-out
RING2_R on TOP: 15.06,12.16 14.91,12.31 14.91,13.17 14.98,13.25 15.52,13.25 15.75,13.48 15.75,14.39 15.77,14.42 16.66,14.42 16.84,14.24 16.84,12.67 16.69,12.51 16.69,12.28 16.56,12.16
RTC_AUX_S5 on TOP: 70.74,2.94 70.53,3.14 70.53,3.55 70.41,3.67 70.33,3.67 70.1,3.9 70.1,4.21 69.8,4.51 69.8,5.58 70.36,6.14 72.52,6.14 72.59,6.06 72.59,5.27 72.41,5.1 71.6,5.1 71.3,4.79 71.3,3.09 71.14,2.94
SLEEVE on TOP: 17.14,14.93 17.04,15.03 17.04,15.61 16.64,16.02 16.53,16.02 16.33,16.22 16.33,16.76 16.41,16.83 16.86,16.83 16.94,16.76 16.94,16.25 17.19,15.99 17.78,15.99 18.06,15.71 18.06,15.05 17.93,14.93
SLEEVE_R on TOP: 17.12,11.42 16.89,11.65 16.89,12.28 17.07,12.46 17.07,14.34 17.17,14.44 18.16,14.44 18.57,14.04 18.82,14.04 18.92,13.94 18.92,13.15 18.57,12.79 18.57,12.26 18.44,12.13 18.13,12.13 17.42,11.42
TP_VDD on TOP: 124.89,18.51 124.51,18.89 124.51,20.29 124.89,20.67 126.29,20.67 126.8,20.16 126.8,18.89 126.41,18.51
TP_VDD on TOP: 131.49,17.49 131.24,17.75 131.24,18 130.99,18.25 130.48,18.25 130.35,18.38 130.35,19.14 130.61,19.4 131.62,19.4 132.38,18.63 132.38,17.49 ; 1 cut-out
TP_VDD on BOTTOM: 126.29,18.38 125.65,19.02 124.26,19.02 123.11,20.16 123.11,21.17 123.24,21.3 126.54,21.3 126.92,21.68 126.92,22.19 127.3,22.57 128.57,22.57 128.7,22.44 128.7,21.68 128.07,21.05 127.56,21.05 127.18,20.67 127.18,19.52 127.43,19.27 127.94,19.27 128.45,19.78 130.22,19.78 130.61,19.4 131.49,19.4 131.62,19.27 131.62,18.89 131.49,18.76 128.32,18.76 127.94,18.38 ; 6 cut-outs
TYPEC_5V_SW on TOP: 44.63,80.61 44.5,80.74 44.5,83.02 44.25,83.28 44.25,85.44 44.37,85.56 46.18,85.56 46.38,85.36 47.78,85.36 47.85,85.28 47.85,81.04 47.42,80.61 ; 2 cut-outs
U3703_OUT on TOP: 28.01,42.74 27.94,42.82 27.94,43.3 27.99,43.35 28.5,43.35 28.73,43.58 28.73,44.97 29.21,45.46 29.21,46.09 29.23,46.12 29.97,46.12 30.07,46.02 30.07,45.36 29.41,44.7 29.41,43.1 29.06,42.74
U3704_OUT on TOP: 22.68,44.85 22.63,44.9 22.63,45.46 22.71,45.53 23.93,45.53 24.18,45.79 24.18,49.09 24.76,49.67 25.35,49.67 25.37,49.65 25.37,48.81 24.76,48.2 24.76,45.61 24,44.85
U4101_OUT on BOTTOM: 109.8,11.35 109.95,11.5 111.48,11.5 111.81,11.17 113.16,11.17 113.31,11.01 113.31,9.39 113.18,9.26 110.06,9.26 109.8,9.52 ; 1 cut-out
USB30_VCCA on BOTTOM: 15.67,55.06 14.96,55.77 14.96,56.66 15.37,57.07 17.19,57.07 17.52,56.73 20.67,56.73 21.39,57.45 21.87,57.45 22.07,57.65 22.76,57.65 22.83,57.57 22.83,55.39 22.76,55.31 22.15,55.31 21.89,55.06 ; 4 cut-outs
USB30_VCCA on L4: 20.98,57.09 22.53,57.09 22.73,56.89 22.73,51.78 24.1,50.41 24.1,50.11 23.85,49.85 20.42,49.85 17.58,52.7 17.58,53.69
USB30_VCCB on TOP: 36.37,47.34 36.12,47.59 36.12,49.75 36.37,50 42.29,50 43.81,51.53 43.81,62.04 43.84,62.07 43.84,62.15 47.17,65.47 47.17,68.55 46.66,69.05 46.66,72.61 46.02,73.24 46.02,77.44 45.79,77.66 43.64,77.66 43.48,77.82 43.48,80.23 43.74,80.48 46.79,80.48 49.07,78.2 49.07,63.36 47.09,61.38 47.09,59.3 48.82,57.57 48.82,51.91 44.25,47.34
USB30_VCCB on TOP: 17.45,40.63 17.83,41.01 20.5,41.01 20.72,40.78 20.72,38.62 22.66,36.69 22.66,35.27 22.02,34.64 20.75,34.64 17.45,37.94
USB30_VCCB on BOTTOM: 20.7,36.49 22.22,36.49 22.22,34.71 22.07,34.56 19.96,34.56 19.63,34.89 19.63,35.93 19.68,35.98 20.19,35.98
USB30_VCCB on BOTTOM: 15.52,35.14 15.01,35.65 15.01,36.87 16.79,38.65 16.79,39.34 16.05,40.07 16.05,41.55 16.23,41.72 20.06,41.72 20.57,41.22 22.05,41.22 22.22,41.04 22.22,40.12 21.97,39.87 20.9,39.87 20.75,39.72 20.75,38.85 20.47,38.57 20.47,38.04 19.81,37.38 18.57,37.38 18.46,37.28 18.46,37.02 18.18,36.75 17.4,36.75 17.22,36.57 17.22,35.37 16.99,35.14 ; 10 cut-outs
USB30_VCCB on L4: 24.48,40.86 25.7,42.08 26.03,42.08 28.32,44.37 29.84,44.37 35.41,49.93 36.83,49.93 37.26,49.5 37.26,47.08 30.66,40.48 28.37,40.48 27.91,40.02 26.36,40.02 25.91,39.56 25.91,37.63 25.2,36.92 19.48,36.92 17.45,38.95 17.45,40.45 18.24,41.24 21.39,41.24 21.77,40.86
USB30_VCCB on L5VCC: 36.32,47.27 36.05,47.54 36.05,49.8 36.32,50.07 42.67,50.07 44.44,51.83 44.44,62.12 47.48,65.16 47.48,72.69 45.96,74.21 45.96,76.85 46.23,77.12 48.61,77.12 49.26,76.47 49.26,63.93 46.85,61.51 46.85,49.96 44.17,47.27
USB_ADT on TOP: 32.03,74.51 31.8,74.74 31.8,77.05 30.91,77.94 30.91,81.25 31.16,81.5 35.36,81.5 36.5,82.64 39.67,82.64 39.95,82.36 40.69,82.36 40.82,82.24 40.82,78.45 40.18,77.82 35.46,77.82 32.82,75.18 32.82,74.67 32.66,74.51 ; 2 cut-outs
USB_ADT on BOTTOM: 150.8,34.51 150.67,34.64 150.67,36.03 150.93,36.29 152.07,36.29 152.58,36.8 153.34,36.8 153.59,36.54 153.59,34.76 153.34,34.51
USBC1_CC1_CONN on TOP: 25.58,41.57 25.07,42.08 24.23,42.08 24.18,42.13 24.18,42.41 24.23,42.46 24.66,42.46 24.84,42.64 25.02,42.64 25.73,43.35 26.72,43.35 26.74,43.32 26.74,42.79 26.85,42.69 26.85,42.23 26.19,41.57
USBC1_CC2_CONN on TOP: 24.2,42.61 24.13,42.69 24.13,42.79 23.9,43.02 23.16,43.02 22.53,43.65 22.53,44.29 22.78,44.54 23.87,44.54 24.89,45.56 24.89,47.03 24.94,47.08 25.42,47.08 25.5,47.01 25.5,45.99 26.01,45.48 26.01,44.92 25.98,44.9 25.09,44.9 24.13,43.93 24.13,43.53 24.34,43.31 24.92,43.31 25.09,43.49 25.09,43.78 25.32,44.01 27.81,44.01 27.91,44.11 27.91,45.2 28.07,45.36 28.4,45.36 28.57,45.18 28.57,43.65 28.4,43.48 25.58,43.48 25.55,43.45 25.55,43.37 24.97,42.79 24.74,42.79 24.56,42.61
V_EDRAM_EOPIO_R on TOP: 102.54,90.9 102.28,91.15 102.28,91.91 102.79,92.42 102.79,93.18 102.67,93.31 100.63,93.31 100.51,93.44 100.51,95.11 100.79,95.39 103.68,95.39 104.39,96.1 105.46,96.1 105.71,95.85 105.71,91.41 105.21,90.9 ; 2 cut-outs
V_EDRAM_EOPIO_R on BOTTOM: 102.41,90.9 102.28,91.02 102.28,92.68 103.05,93.44 104.95,93.44 105.08,93.31 105.08,92.17 104.82,91.91 103.94,91.91 103.68,91.66 103.68,91.02 103.55,90.9

Small or netless copper shapes (teardrops, artwork), in the pictures only: 1 on TOP, 2 on BOTTOM

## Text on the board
Ref Des/Silkscreen Bottom: 15BBY | 15ROR | M2L2 | 13BBY | 13ROR | 17BBY | M2L2 17BBY | X1802:32.768KHZ | F6501:.5A/6V | X1801:24MHZ | FAN1:CON4 | Only support DDR4 | DIMM2 | DIMM1 | MADE IN TAIWAN | X41DX | 15264-1 | Starlord13_B
Ref Des/Silkscreen Top: F5504:1.1A/6V | F5502:.5A/6V | X2401:32.768KHZ | X6901:12MHZ | F5701:1.1A/6V | F5503:1.1A/24V | F5501:1.1A/24V
User.28: ByImpedance:100.0@_REF_L1=("nil(L1)")|_REF_L6=("4.0/10.0(L6)")|Type="DP"|_REF_L4=("4.0/6.5(L4)")|_REF_L3=("4.0/6.5(L3)" "4.0/10.0(L3)")|imp="100.0"|_REF_L8=("nil(L8)") | ByImpedance:33.0@_REF_L1=("8.0(L1)")|_REF_L6=("9.0(L6)")|Type="SE"|_REF_L4=("11.0(L4)")|_REF_L3=("11.0(L3)" "9.0(L3)")|imp="33.0"|_REF_L8=("8.0(L8)") | ByImpedance:35.0@_REF_L1=("7.5(L1)")|_REF_L6=("8.5(L6)")|Type="SE"|_REF_L4=("10.0(L4)")|_REF_L3=("10.0(L3)" "8.5(L3)")|imp="35.0"|_REF_L8=("7.5(L8)") | ByImpedance:37.5@_REF_L1=("6.5(L1)")|_REF_L6=("7.5(L6)")|Type="SE"|_REF_L4=("9.0(L4)")|_REF_L3=("7.5(L3)" "9.0(L3)")|imp="37.5"|_REF_L8=("6.5(L8)") | ByImpedance:40.0@_REF_L1=("6.0(L1)")|_REF_L6=("6.5(L6)")|Type="SE"|_REF_L4=("8.0(L4)")|_REF_L3=("6.5(L3)" "8.0(L3)")|imp="40.0"|_REF_L8=("6.0(L8)") | ByImpedance:45.0@_REF_L1=("4.5(L1)")|_REF_L6=("5.0(L6)")|Type="SE"|_REF_L4=("6.5(L4)")|_REF_L3=("6.5(L3)" "5.0(L3)")|imp="45.0"|_REF_L8=("4.5(L8)") | ByImpedance:50.0@_REF_L1=("3.5(L1)")|_REF_L6=("4.0(L6)")|Type="SE"|_REF_L4=("5.0(L4)")|_REF_L3=("4.0(L3)" "5.0(L3)")|imp="50.0"|_REF_L8=("3.5(L8)") | ByImpedance:55.0@_REF_L1=("nil(L1)")|_REF_L6=("nil(L6)")|Type="SE"|_REF_L4=("4.0(L4)")|_REF_L3=("4.0(L3)")|imp="55.0"|_REF_L8=("nil(L8)") | ByImpedance:60.0@_REF_L1=("7.5/4.0(L1)")|_REF_L6=("9.5/4.5(L6)")|Type="DP"|_REF_L4=("10.5/4.5(L4)")|_REF_L3=("10.5/4.5(L3)" "9.5/4.5(L3)")|imp="60.0"|_REF_L8=("7.5/4.0(L8)") | ByImpedance:63.0@_REF_L1=("7.0/4.5(L1)")|_REF_L6=("8.5/4.0(L6)")|Type="DP"|_REF_L4=("9.5/4.0(L4)")|_REF_L3=("8.5/4.0(L3)" "9.5/4.0(L3)")|imp="63.0"|_REF_L8=("7.0/4.5(L8)") | ByImpedance:70.0@_REF_L1=("6.0/5.0(L1)")|_REF_L6=("7.0/5.0(L6)")|Type="DP"|_REF_L4=("8.5/5.0(L4)")|_REF_L3=("7.0/5.0(L3)" "8.5/5.0(L3)")|imp="70.0"|_REF_L8=("6.0/5.0(L8)") | ByImpedance:72.0@_REF_L1=("5.5/4.5(L1)")|_REF_L6=("6.5/4.5(L6)")|Type="DP"|_REF_L4=("7.5/5.0(L4)")|_REF_L3=("7.5/5.0(L3)" "6.5/4.5(L3)")|imp="72.0"|_REF_L8=("5.5/4.5(L8)") | ByImpedance:75.0@_REF_L1=("5.0/4.5(L1)")|_REF_L6=("6.0/4.5(L6)")|Type="DP"|_REF_L4=("7.0/5.0(L4)")|_REF_L3=("7.0/5.0(L3)" "6.0/4.5(L3)")|imp="75.0"|_REF_L8=("5.0/4.5(L8)") | ByImpedance:80.0@_REF_L1=("4.5/5.0(L1)")|_REF_L6=("5.5/5.0(L6)")|Type="DP"|_REF_L4=("6.0/5.0(L4)")|_REF_L3=("5.5/5.0(L3)" "6.0/5.0(L3)")|imp="80.0"|_REF_L8=("4.5/5.0(L8)") | ByImpedance:83.0@_REF_L1=("3.5/4.0(L1)")|_REF_L6=("5.0/4.0(L6)")|Type="DP"|_REF_L4=("5.5/4.5(L4)")|_REF_L3=("5.5/4.5(L3)" "5.0/4.0(L3)")|imp="83.0"|_REF_L8=("3.5/4.0(L8)") | ByImpedance:85.0@_REF_L1=("4.0/5.0(L1)")|_REF_L6=("5.0/5.5(L6)")|Type="DP"|_REF_L4=("5.5/5.0(L4)")|_REF_L3=("5.5/5.0(L3)" "5.0/5.5(L3)")|imp="85.0"|_REF_L8=("4.0/5.0(L8)") | ByImpedance:88.0@_REF_L1=("4.0/7.0(L1)")|_REF_L6=("4.0/4.0(L6)")|Type="DP"|_REF_L4=("5.0/5.0(L4)")|_REF_L3=("4.0/4.0(L3)" "5.0/5.0(L3)")|imp="88.0"|_REF_L8=("4.0/7.0(L8)") | ByImpedance:90.0@_REF_L1=("4.0/8.0(L1)" "3.5/6.0(L1)")|_REF_L6=("4.0/4.5(L6)")|Type="DP"|_REF_L4=("5.0/6.0(L4)")|_REF_L3=("5.0/6.0(L3)" "4.0/4.5(L3)")|imp="90.0"|_REF_L8=("4.0/8.0(L8)" "3.5/6.0(L8)") | LayerIndex:nil | Source:8-1.0-16f.xls | artWorks:("_REF_L3" "_REF_L6" "_REF_L4" "_REF_L8" "_REF_L1") | gtImpOutlineUsed:BOARD GEOMETRY/PANEL_OUTLINE
User.29: Board Accuracy Check,Jan 13 16:12:07 2016,Passed | Dummy-Static-No Shape On Layer Check,Jan 13 16:12:08 2016,Passed | Split Plane Check,Jan 12 20:44:59 2016,Passed
User.34: This gerber is just for your reference to find the DP impedance traces in layer L1. | DP IMPEDANCE TABLE: L1 | * - Denotes that this Impedance | is NOT used | IMP(Ohm) | *60.0 | *63.0 | *70.0 | *72.0 | *75.0 | *80.0 | *83.0 | 85.0 | *88.0 | *90.0 | *100.0 | WIDTH(mils) | 7.5/4.0 | 7.0/4.5 | 6.0/5.0 | 5.5/4.5 | 5.0/4.5 | 4.5/5.0 | 3.5/4.0 | 4.0/5.0 | 4.0/7.0 | 4.0/8.0 | 3.5/6.0 | nil | TYPE | DP
User.36: This gerber is just for your reference to find the SE impedance traces in layer L1. | SE IMPEDANCE TABLE: L1 | * - Denotes that this Impedance | is NOT used | IMP(Ohm) | *33.0 | *35.0 | *37.5 | 40.0 | *45.0 | 50.0 | *55.0 | WIDTH(mils) | 8.0 | 7.5 | 6.5 | 6.0 | 4.5 | 3.5 | nil | TYPE | SE
User.38: This gerber is just for your reference to find the DP impedance traces in layer L3. | DP IMPEDANCE TABLE: L3 | * - Denotes that this Impedance | is NOT used | IMP(Ohm) | *60.0 | *63.0 | *70.0 | *72.0 | *75.0 | *80.0 | 83.0 | *83.0 | 85.0 | *85.0 | *88.0 | *90.0 | *100.0 | WIDTH(mils) | 10.5/4.5 | 9.5/4.5 | 8.5/4.0 | 9.5/4.0 | 7.0/5.0 | 8.5/5.0 | 7.5/5.0 | 6.5/4.5 | 6.0/4.5 | 5.5/5.0 | 6.0/5.0 | 5.5/4.5 | 5.0/4.0 | 5.0/5.5 | 4.0/4.0 | 5.0/5.0 | 5.0/6.0 | 4.0/4.5 | 4.0/6.5 | 4.0/10.0 | TYPE | DP
User.40: This gerber is just for your reference to find the SE impedance traces in layer L3. | SE IMPEDANCE TABLE: L3 | * - Denotes that this Impedance | is NOT used | IMP(Ohm) | *33.0 | *35.0 | *37.5 | *40.0 | 40.0 | *45.0 | *50.0 | 50.0 | *55.0 | WIDTH(mils) | 11.0 | 9.0 | 10.0 | 8.5 | 7.5 | 6.5 | 8.0 | 5.0 | 4.0 | TYPE | SE
User.42: This gerber is just for your reference to find the DP impedance traces in layer L4. | DP IMPEDANCE TABLE: L4 | * - Denotes that this Impedance | is NOT used | IMP(Ohm) | *60.0 | *63.0 | *70.0 | *72.0 | *75.0 | *80.0 | *83.0 | *85.0 | *88.0 | *90.0 | *100.0 | WIDTH(mils) | 10.5/4.5 | 9.5/4.0 | 8.5/5.0 | 7.5/5.0 | 7.0/5.0 | 6.0/5.0 | 5.5/4.5 | 5.5/5.0 | 5.0/5.0 | 5.0/6.0 | 4.0/6.5 | TYPE | DP
User.44: This gerber is just for your reference to find the SE impedance traces in layer L4. | SE IMPEDANCE TABLE: L4 | * - Denotes that this Impedance | is NOT used | IMP(Ohm) | *33.0 | *35.0 | *37.5 | *40.0 | *45.0 | 50.0 | *55.0 | WIDTH(mils) | 11.0 | 10.0 | 9.0 | 8.0 | 6.5 | 5.0 | 4.0 | TYPE | SE
User.45: Note:Refer to DRILL layer for ELLIPSE drill direction | FIGURE | SIZE | 10.0 | 16.0 | 21.0 | 32.0 | 115.0 | 178.0 | 229.0 | 28.0 | 30.0 | 36.0 | 38.0 | 44.0 | 46.0 | 63.0 | 65.0 | 71.0 | 86.0 | 91.0 | 107.0 | 113.0 | 158.0 | 36.0x16.0 | 44.0x20.0 | 58.0x26.0 | 60.0x36.0 | 63.0x24.0 | 71.0x36.0 | 90.0x28.0 | 157.0x118.0 | DRILL CHART: TOP to BOTTOM | ALL UNITS ARE IN MILS | PLATED | NON-PLATED | QTY | 3594 | 784 | 19 | 18 | 1 | 6 | 3 | 4 | 2 | 7 | This gerber is just for your reference to find the DP impedance traces in layer L6. | This gerber is just for your reference to find the DP impedance traces in layer L8. | This gerber is just for your reference to find the SE impedance traces in layer L6. | This gerber is just for your reference to find the SE impedance traces in layer L8. | DP IMPEDANCE TABLE: L6 | DP IMPEDANCE TABLE: L8 | SE IMPEDANCE TABLE: L6 | SE IMPEDANCE TABLE: L8 | * - Denotes that this Impedance | is NOT used | Model | Starlord13_B | PCB_NO | 15264 | VER. | Layer | DRILL | L1 | L2GND | L3 | L4 | TMASK | TPLACE | TSILK | TSMD | Designer | JERRY J | Date | 02/26/2016 | IMP(Ohm) | *33.0 | *60.0 | *35.0 | *63.0 | *37.5 | *70.0 | *72.0 | 40.0 | *45.0 | *75.0 | *80.0 | 50.0 | *55.0 | 83.0 | 85.0 | *88.0 | *90.0 | *100.0 | WIDTH(mils) | 8.0 | 9.0 | 7.5 | 8.5 | 6.5 | 6.0 | 4.5 | 5.0 | 3.5 | 4.0 | nil | 7.5/4.0 | 7.0/4.5 | 6.0/5.0 | 5.5/4.5 | 5.0/4.5 | 4.5/5.0 | 3.5/4.0 | 4.0/5.0 | 4.0/7.0 | 4.0/8.0 | 3.5/6.0 | 9.5/4.5 | 8.5/4.0 | 7.0/5.0 | 6.5/4.5 | 6.0/4.5 | 5.5/5.0 | 5.0/4.0 | 5.0/5.5 | 4.0/4.0 | 4.0/4.5 | 4.0/10.0 | TYPE | SE | DP | BMASK | BPLACE | BSILK | BSMD | L5VCC | L6 | L7GND | L8
